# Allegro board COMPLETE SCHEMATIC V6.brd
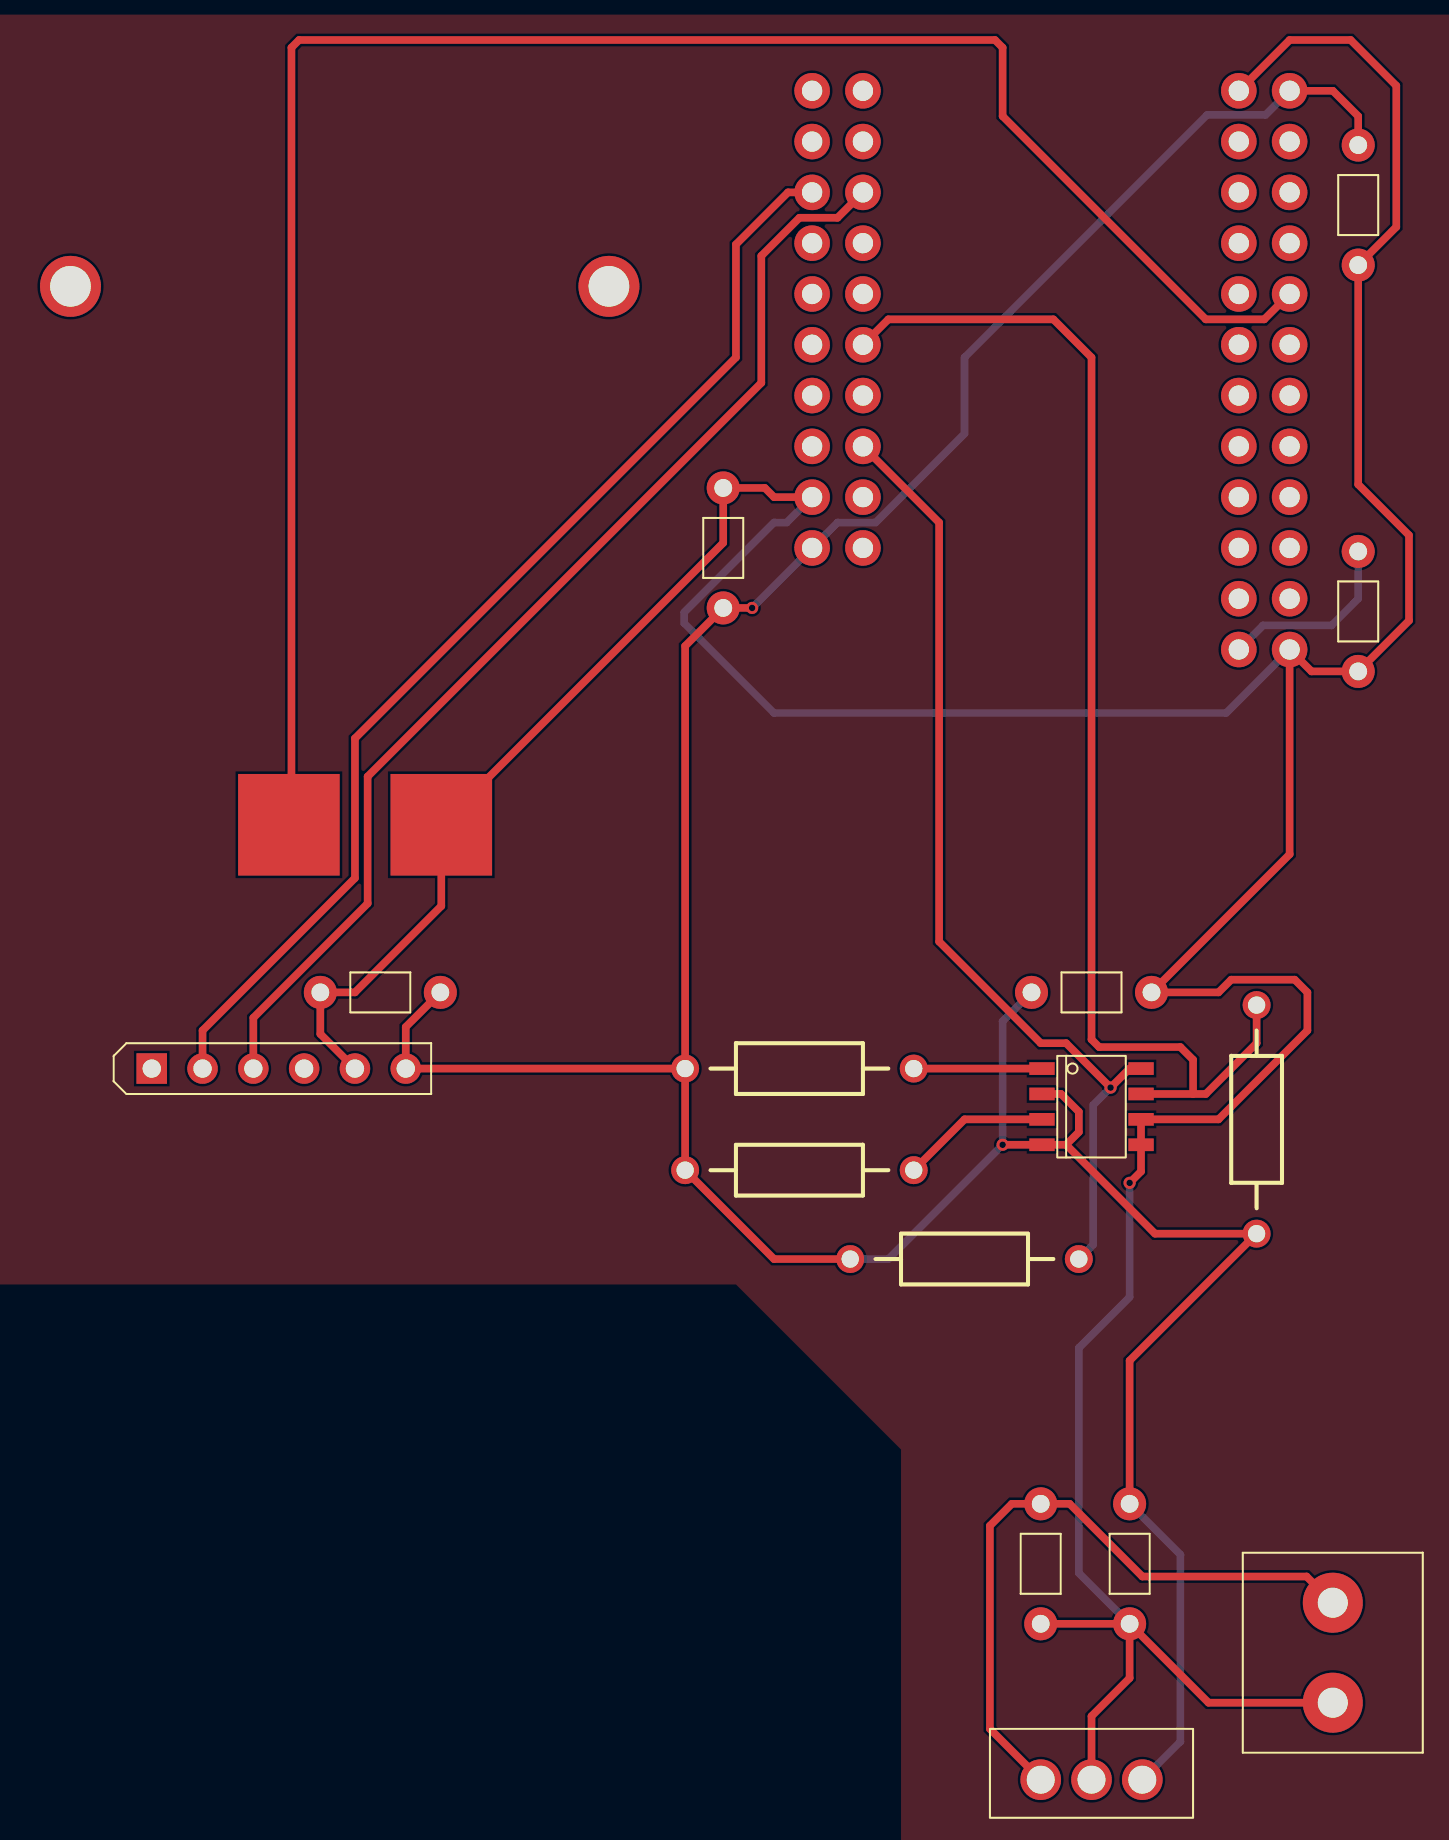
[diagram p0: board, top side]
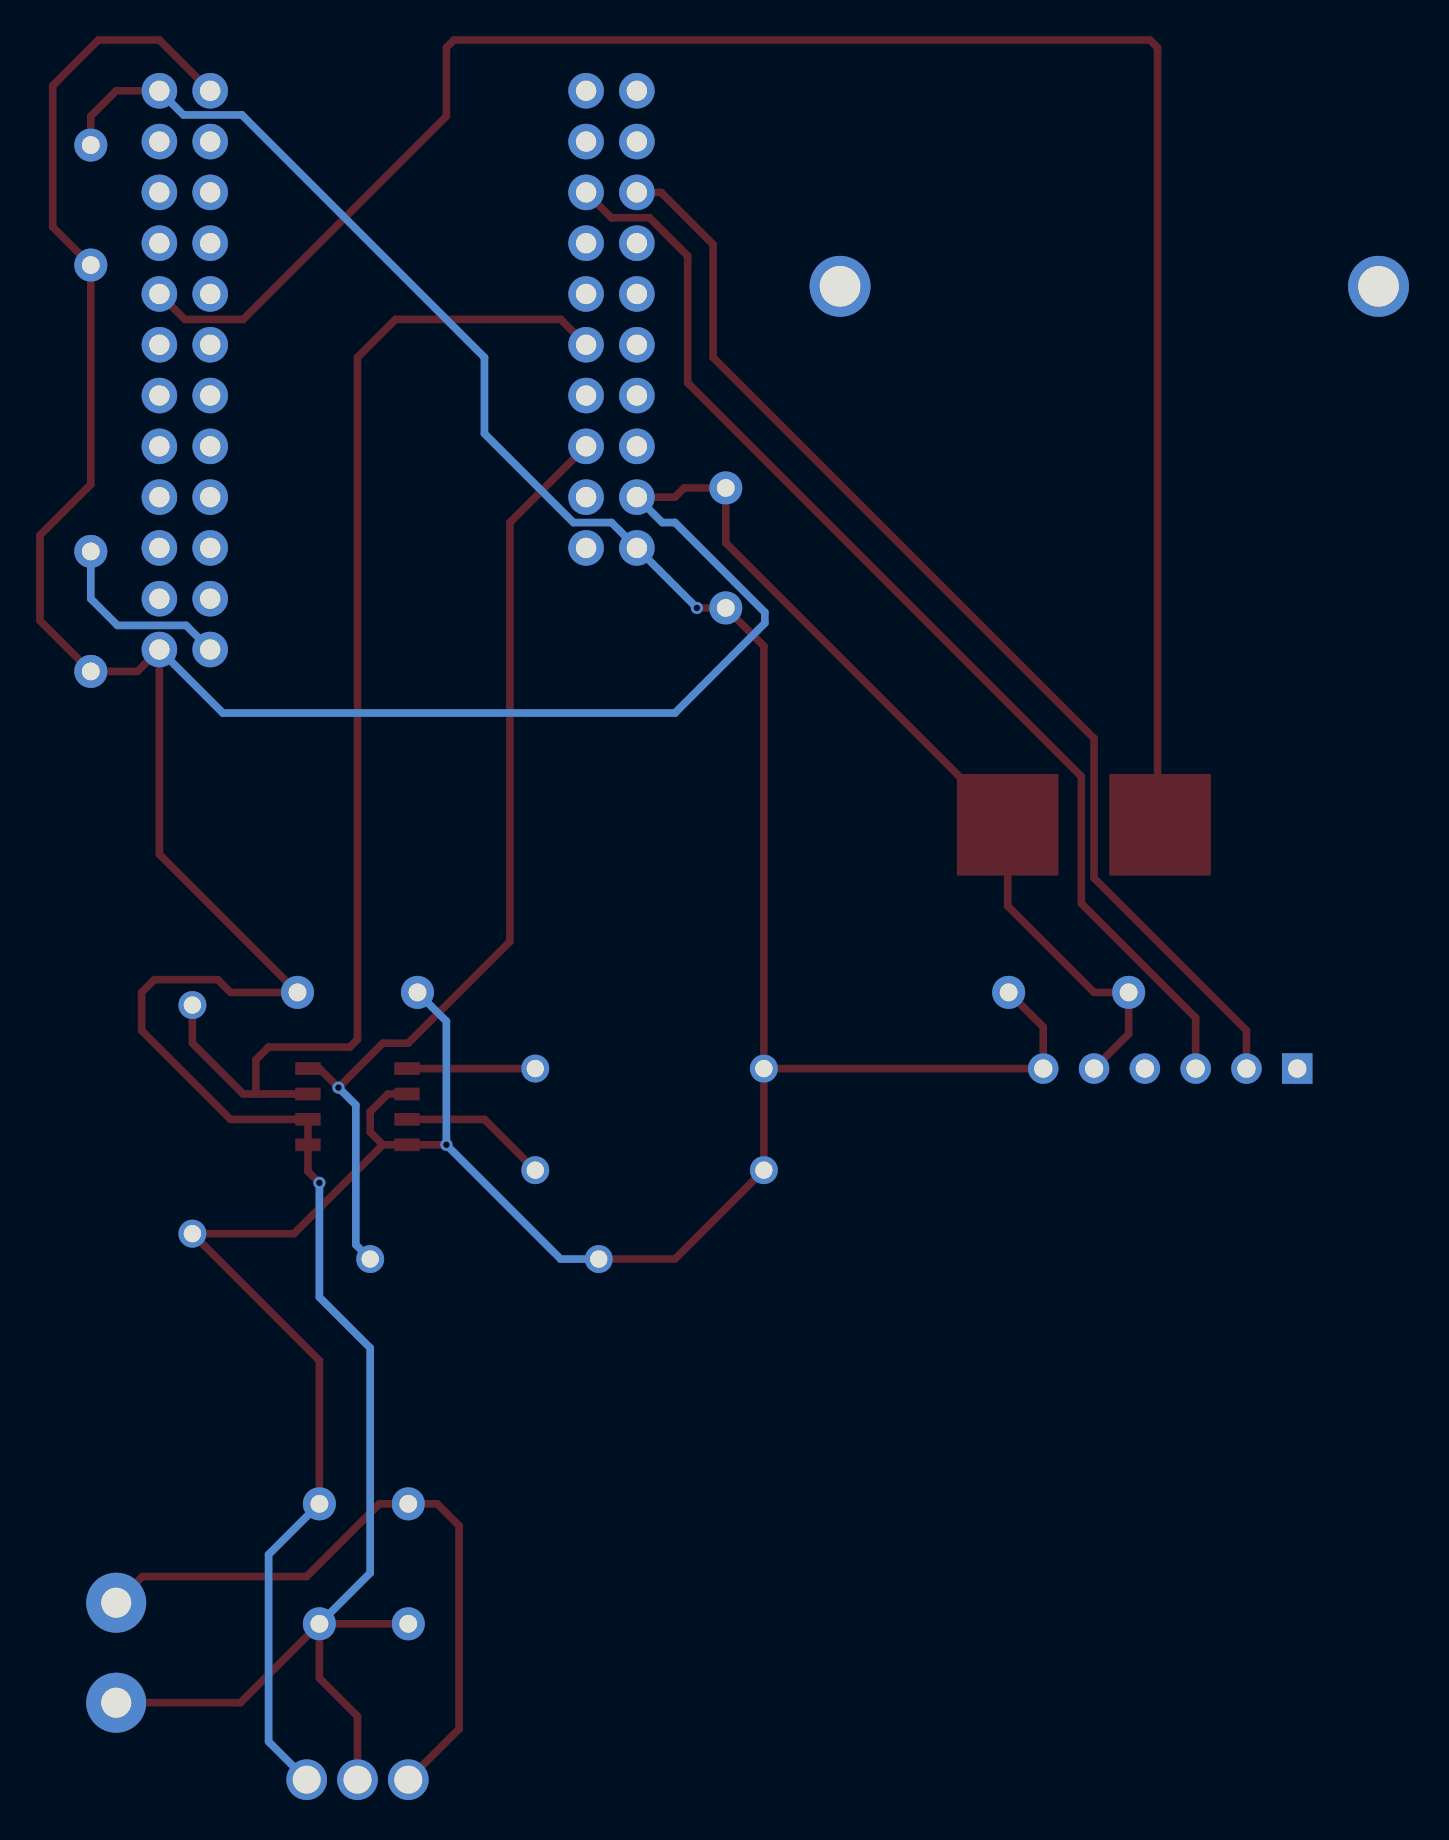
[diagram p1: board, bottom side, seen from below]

No outline. copper layers: TOP, BOTTOM. Coordinates in mm from the lowest, leftmost part position.

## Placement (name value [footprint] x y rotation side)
BT1  BATTERY  [2POS5MMCON]  59.06 6.35 0 top
C1  0.33uF 50V  [CAP1]  44.45 10.8 270 top
C2  0.1uF 50V  [CAP1]  48.9 10.8 270 top
C4  0.1uF 50V  [CAP1]  28.58 61.59 90 top
C5  0.1 uF 50V  [CAP1]  60.33 78.74 270 top
C6  0.1uF 50V  [CAP1]  60.33 58.42 270 top
C7  0.1uF 50V  [CAP1]  11.43 39.37 0 top
C8  CAP NP  [CAP1]  46.99 39.37 0 top
J1  HEADER 6  [SIP6]  0 35.56 90 top
LS1  -  [BUZZER]  25.4 85.72 0 top
R14  R  [AXRC07]  34.93 26.03 0 top
R15  R  [AXRC07]  55.25 27.31 90 top
R16  R  [AXRC07]  26.67 30.48 0 top
R17  R  [AXRC07]  26.67 35.56 0 top
U1  LM7805  [TO220AB]  44.45 0 180 top
U3  PSoC4BLE  [PSOC4BLE]  33.02 84.46 0 top
U5  ds3231  [SOIC8]  46.99 33.66 0 top

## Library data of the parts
BT1 = BATTERY
C1 C2 C4-C8 = CAP NP
J1 = HEADER 6_0: User Part Number: ***
LS1 = BUZZER
R14-R17 = R
U1 = Linear regulator
U3 = PSoC4BLE_0
U5 = ds3231_0: Tolerance: ***; User Part Number: ***

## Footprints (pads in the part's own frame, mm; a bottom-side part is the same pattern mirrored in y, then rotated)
2POS5MMCON
  round 3 hole 1.5: 1(0,2.5) 2(0,-2.5)
AXRC07
  round 1.397 hole 0.864: 1(0,0) 2(11.43,0)
BUZZER
  round 3.048 hole 2.032: (-29.464,-11.049) (-2.54,-11.049)
  rect 5.08x5.08 smd: 1(-18.542,-37.973) 2(-10.922,-37.973)
CAP1
  round 1.651 hole 0.889: 1(-3,0) 2(3,0)
PSOC4BLE
  round 1.778 hole 1.016: 1(2.54,-22.86) 2(0,-22.86) 3(2.54,-20.32) 4(0,-20.32) 5(2.54,-17.78) 6(0,-17.78) 7(2.54,-15.24) 8(0,-15.24) 9(2.54,-12.7) 10(0,-12.7) 11(2.54,-10.16) 12(0,-10.16) 13(2.54,-7.62) 14(0,-7.62) 15(2.54,-5.08) 16(0,-5.08) 17(2.54,-2.54) 18(0,-2.54) 19(2.54,0) 20(0,0) 21(21.336,0) 22(23.876,0) 23(21.336,-2.54) 24(23.876,-2.54) 25(21.336,-5.08) 26(23.876,-5.08) 27(21.336,-7.62) 28(23.876,-7.62) 29(21.336,-10.16) 30(23.876,-10.16) 31(21.336,-12.7) 32(23.876,-12.7) 33(21.336,-15.24) 34(23.876,-15.24) 35(21.336,-17.78) 36(23.876,-17.78) 37(21.336,-20.32) 38(23.876,-20.32) 39(21.336,-22.86) 40(23.876,-22.86) 41(21.336,-25.4) 42(23.876,-25.4) 43(21.336,-27.94) 44(23.876,-27.94)
SIP6
  rect 1.524x1.524 hole 0.914: 1(0,0)
  round 1.524 hole 0.914: 2(0,-2.54) 3(0,-5.08) 4(0,-7.62) 5(0,-10.16) 6(0,-12.7)
SOIC8
  rect 1.27x0.635 smd: 1(-2.477,1.905) 2(-2.477,0.635) 3(-2.477,-0.635) 4(-2.477,-1.905) 5(2.477,-1.905) 6(2.477,-0.635) 7(2.477,0.635) 8(2.477,1.905)
TO220AB
  round 2.032 hole 1.397: 1(0,0) 2(-2.54,0) 3(-5.08,0)

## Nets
+VBAT: BT1.1(+) C1.1 U1.1(INPUT)
GND: BT1.2(-) C1.2 C2.2 C4.2 C5.2 C6.2 C7.1 C8.2 J1.5(GND) LS1.2(B) U1.2(GEOUND) U3.4(GND1) U3.21(GND2) U3.44(GND3) U5.5(GND) U5.6(VBAT)
+5 V: C2.1 C4.1 C5.1 C7.2 C8.1 J1.6(VCC) R14.1 R15.1 R16.1 R17.1 U1.3(OUTPUT) U3.2(VDDD) U3.22(VDDA) U5.2(VCC) U5.4(R\S\T\)
RXD: J1.2(RXD) U3.16(P0.5)
SCL: R14.2 U3.5(P1.5) U5.8(SCL)
SDA: R15.2 U3.9(P1.4) U5.7(SDA)
TXD: J1.3(TXD) U3.15(P0.4)
N57082: C6.1 U3.43(VDDR)
N86841: R16.2 U5.3(I\N\T\/SQW)
N86845: R17.2 U5.1(32KHZ)
N89522: LS1.1(A) U3.30(P3.1)

Pads without a net: J1 1 4; U3 1 3 6 7 8 10 11 12 13 14 17 18 19 20 23 24 25 26 27 28 29 31 32 33 34 35 36 37 38 39 40 41 42

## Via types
v1: diameter 0.61, hole 0.33, TOP to BOTTOM, 4 vias

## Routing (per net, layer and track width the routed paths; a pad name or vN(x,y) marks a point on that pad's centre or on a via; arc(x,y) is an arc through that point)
+VBAT: length 33.4
  TOP w0.381: BT1.1 57.75,10.16 49.53,10.16 45.9,13.79 C1.1 43,13.79 41.91,12.7 41.91,2.54 U1.1
GND: length 225.2
  TOP w0.381: C2.2 48.9,5.08 46.99,3.18 U1.2 ; C2.2 C1.2 ; C2.2 52.84,3.85 BT1.2 ; J1.5 8.43,37.29 C7.1 10.16,39.37 14.48,43.69 LS1.2 28.58,61.85 C4.2 30.66,64.59 31.12,64.14 U3.4 ; U3.21 56.9,87 59.94,87 62.23,84.71 62.23,77.65 C5.2 60.33,64.77 62.87,62.23 62.87,57.96 C6.2 57.99,55.42 U3.44 56.9,46.28 C8.2 53.34,39.37 53.97,40.01 57.15,40.01 57.78,39.37 57.78,37.47 53.34,33.02 U5.6 U5.5 49.47,30.42 v1(48.9,29.84)
  BOTTOM w0.381: U3.4 31.75,62.87 31.12,62.87 26.62,58.37 26.62,57.83 31.12,53.34 53.72,53.34 U3.44 ; v1(48.9,29.84) 48.9,24.13 46.36,21.59 46.36,10.34 C2.2
+5 V: length 172.8
  TOP w0.381: 45.72,31.75 50.17,27.31 R15.1 48.9,20.96 C2.1 ; 45.72,31.75 46.36,32.39 46.36,33.4 45.47,34.29 U5.2 ; 45.72,31.75 U5.4 v1(42.55,31.75) ; C7.2 12.7,37.64 J1.6 R17.1 ; R14.1 31.12,26.03 R16.1 R17.1 ; R17.1 26.67,56.69 C4.1 v1(30.02,58.6) ; U3.22 59.06,84.46 60.33,83.19 C5.1
  BOTTOM w0.381: R14.1 36.83,26.03 v1(42.55,31.75) 42.55,37.92 C8.1 ; U1.3 51.44,1.91 51.44,11.25 C2.1 ; v1(30.02,58.6) U3.2 34.29,62.87 36.2,62.87 40.64,67.31 40.64,71.12 52.77,83.25 55.69,83.25 U3.22
RXD: length 57.1
  TOP w0.381: J1.2 2.54,37.47 10.16,45.09 10.16,52.07 29.21,71.12 29.21,76.77 31.81,79.38 U3.16
SCL: length 49.2
  TOP w0.381: 49.53,35.56 U5.8 48.9,35.56 v1(47.94,34.61) 45.72,36.83 44.45,36.83 39.37,41.91 39.37,62.87 U3.5
  BOTTOM w0.381: R14.2 47.07,26.75 47.07,33.74 v1(47.94,34.61)
SDA: length 63.1
  TOP w0.381: 52.07,34.29 U5.7 49.15,34.29 ; 52.07,34.29 52.71,34.29 55.25,36.83 R15.2 ; 52.07,34.29 52.07,36 51.44,36.63 47.37,36.63 46.99,37.02 46.99,71.12 45.09,73.03 36.83,73.03 U3.9
TXD: length 57.6
  TOP w0.381: U3.15 34.29,78.1 32.39,78.1 30.48,76.2 30.48,69.85 10.8,50.16 10.8,43.82 5.08,38.1 J1.3
N57082: length 9.4
  BOTTOM w0.381: U3.43 55.56,57.72 58.99,57.72 60.33,59.06 C6.1
N86841: length 7.5
  TOP w0.381: R16.2 40.64,33.02 U5.3
N86845: length 6.4
  TOP w0.381: R17.2 U5.1
N89522: length 97.3
  TOP w0.381: U3.30 55.63,73.03 52.71,73.03 42.55,83.19 42.55,86.61 42.16,87 7.37,87 6.99,86.61 6.99,47.88 LS1.1

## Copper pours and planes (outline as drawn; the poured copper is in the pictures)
Net_1 on TOP: 66.37,-4.44 66.37,87 65.1,88.27 -9.52,88.27 -10.79,87 -10.79,25.81 -9.75,24.77 29.21,24.77 37.47,16.51 37.47,-4.44 38.74,-5.71 65.1,-5.71
